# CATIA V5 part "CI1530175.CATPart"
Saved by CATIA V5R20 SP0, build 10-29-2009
Part number: CI1530175
Bounding box of the stored display mesh (mm): x -29 to 29, y -25.332 to 220, z -36.193 to 33.549
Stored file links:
  C:\Users\Raffaele\Desktop\3D X SITO CF\BOLEX\19-INCLINED ASSEMBLY REF_CI\CI1530175.CATPart

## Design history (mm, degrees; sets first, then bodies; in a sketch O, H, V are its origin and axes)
Set1
  DatumSurface1 to DatumSurface16 "MANIFOLD_SOLID_BREP #395"
  DatumSurface17 to DatumSurface39 "MANIFOLD_SOLID_BREP #1144"
Body1 (main body)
